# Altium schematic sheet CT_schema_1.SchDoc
size 328 x 203 mm
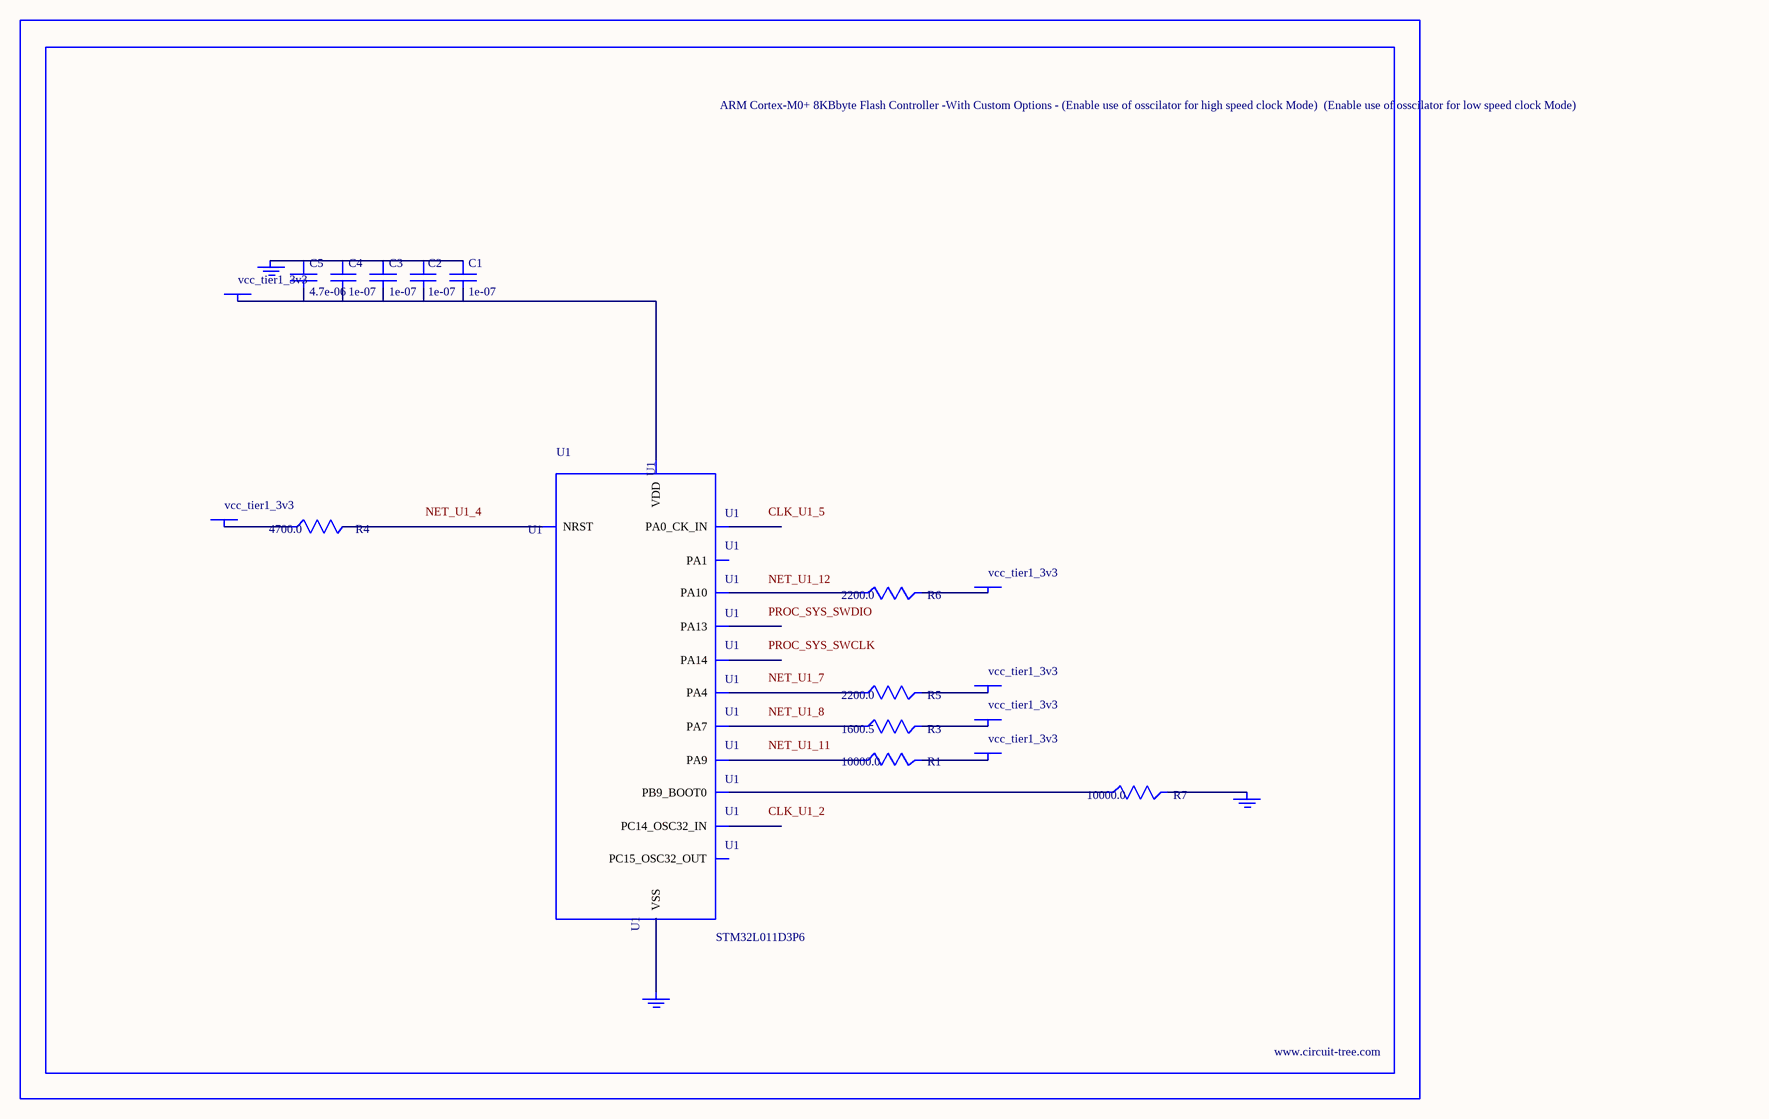
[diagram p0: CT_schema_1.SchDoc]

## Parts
BORDER0  (no value)
C1  1e-07  [C0603]
C2  1e-07  [C0603]
C3  1e-07  [C0603]
C4  1e-07  [C0603]
C5  4.7e-06  [C0603]
GND_INSTANCE_0_0  (no value)
GND_INSTANCE_0_1  (no value)
GND_INSTANCE_0_2  (no value)
POWER_INSTANCE_0_0  vcc_tier1_3v3
POWER_INSTANCE_0_1  vcc_tier1_3v3
POWER_INSTANCE_0_2  vcc_tier1_3v3
POWER_INSTANCE_0_3  vcc_tier1_3v3
POWER_INSTANCE_0_4  vcc_tier1_3v3
POWER_INSTANCE_0_5  vcc_tier1_3v3
R1  10000.0  [R0603]
R3  1600.5  [R0603]
R4  4700.0  [R0603]
R5  2200.0  [R0603]
R6  2200.0  [R0603]
R7  10000.0  [R0603]
U1  STM32L011D3P6  [TSSOP14]

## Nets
NetC1_1: C1.1 C2.1 C3.1 C4.1 C5.1 GND_INSTANCE_0_1.0(GND)
NetC1_2: C1.2 C2.2 C3.2 C4.2 C5.2 POWER_INSTANCE_0_0.0(PWR) U1.10(VDD)
NetGND_INSTANCE_0_0_0: GND_INSTANCE_0_0.0(GND) R7.2
NetGND_INSTANCE_0_2_0: GND_INSTANCE_0_2.0(GND) U1.9(VSS)
NetPOWER_INSTANCE_0_1_0: POWER_INSTANCE_0_1.0(PWR) R4.1
NetPOWER_INSTANCE_0_2_0: POWER_INSTANCE_0_2.0(PWR) R5.2
NetPOWER_INSTANCE_0_3_0: POWER_INSTANCE_0_3.0(PWR) R3.2
NetPOWER_INSTANCE_0_4_0: POWER_INSTANCE_0_4.0(PWR) R1.2
NetPOWER_INSTANCE_0_5_0: POWER_INSTANCE_0_5.0(PWR) R6.2
NetR1_1: R1.1 U1.11(PA9)
NetR3_1: R3.1 U1.8(PA7)
NetR4_2: R4.2 U1.4(NRST)
NetR5_1: R5.1 U1.7(PA4)
NetR6_1: R6.1 U1.12(PA10)
NetR7_1: R7.1 U1.1(PB9_BOOT0)

Not connected (* = marked no-connect by the designer): U1 2(PC14_OSC32_IN) 3(PC15_OSC32_OUT) 5(PA0_CK_IN) 6(PA1) 13(PA13) 14(PA14)

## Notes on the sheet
- Labels drawn without touching a wire or pin: CLK_U1_2, CLK_U1_5, NET_U1_4, NET_U1_7, NET_U1_8, NET_U1_11, NET_U1_12, PROC_SYS_SWCLK, PROC_SYS_SWDIO

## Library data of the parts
BORDER0 = BORDER_PAGE0
C1-C4 = 06035C104K4Z2A
C5 = GRM188R6YA475KE15D
GND_INSTANCE_0_0-GND_INSTANCE_0_2 = GND
POWER_INSTANCE_0_0-POWER_INSTANCE_0_5 = PWR
R1 R7 = RC0603JR-0710KL
R3 = R3
R4 = RC0603JR-074K7L
R5 R6 = RC0603JR-072K2L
